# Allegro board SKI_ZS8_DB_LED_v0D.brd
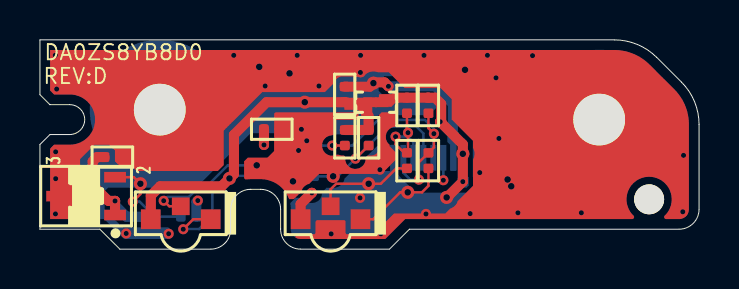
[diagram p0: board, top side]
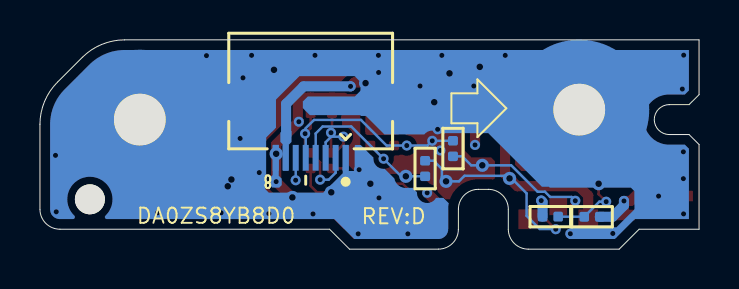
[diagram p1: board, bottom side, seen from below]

Outline 33 x 10.5 mm; copper layers: TOP, SGND, IN1, IN2, SVCC, IN3, SGND1, BOTTOM. Coordinates in mm from the lower left corner of the outline.
Outline path: 0,10.5 28.76,10.5 arc(29.91,10.27) 30.88,9.62 32.12,8.38 arc(32.77,7.41) 33,6.26 33,2 arc(32.71,1.29) 32,1 18.5,1 17.5,0 13.05,0 arc(12.34,0.29) 12.05,1 12.05,2 arc(11.76,2.71) 11.05,3 10.55,3 arc(9.84,2.71) 9.55,2 9.55,1 arc(9.26,0.29) 8.55,0 4,0 3,1 0,1 0,5.25 0.5,5.75 1.5,5.75 arc(2.25,6.5) 1.5,7.25 0.5,7.25 0,7.75 0,10.5

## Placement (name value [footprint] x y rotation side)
C7  0.1u/10v_4  [CC0402]  3.63 4.62 180 top
CN5048  led db  [50501-0080N-001-8P-L]  19.44 7.38 0 bottom
D4  *0.2pf/5v_4  [RC0402]  11.61 6.02 180 top
D6  *0.2pf/5v_4  [RC0402]  7.44 1.63 180 bottom
HE1  em-6781-t3  [SOT23_123-2_8-1_9]  2.31 2.66 0 top
HOLE1  *h-tc276bc102d102pt  [H-TC276BC102D102PT]  28 6.5 180 bottom
HOLE2  *h-c59d59n  [H-C59D59N]  30.5 2.5 0 top
HOLE3  *h-tc276bc102d102pt  [H-TC276BC102D102PT]  6 7 180 bottom
LED1  dual_light  [LEDLTST-S326KGJRKT-3P-SMT]  7.05 1.5 180 top
LED2  dual_light  [LEDLTST-S326KGJRKT-3P-SMT]  14.55 1.5 180 top
NOREF  -  []  -34.82 -54.97 0 top
NOREF#2  -  []  17.63 31.5 0 top
R1  *1m_4  [RC0402]  15.27 5.59 270 top
R2  *1m_4  [RC0402]  16.46 5.59 270 top
R3  300_4  [RC0402]  12.32 5.05 90 bottom
R4  680_4  [RC0402]  13.71 4.04 270 bottom
R5  *1m_4  [RC0402]  18.38 7.21 270 top
R6  *1m_4  [RC0402]  19.45 7.21 270 top
R7  300_4  [RC0402]  18.38 4.44 90 top
R8  680_4  [RC0402]  19.45 4.44 90 top
R9  *0_4  [RC0402]  15.26 7.76 90 top
R10  *short_4  [SHORT0402]  16.83 7.37 0 top
R11  *100k_4  [RC0402]  5.36 1.62 0 bottom

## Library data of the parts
C7 = CC0402
CN5048 = 50501-0080N-001-8P-L
D4 D6 R1-R9 R11 = RC0402
HE1 = SOT23_123-2_8-1_9
HOLE1 HOLE3 = H-TC276BC102D102PT
HOLE2 = H-C59D59N
LED1 LED2 = LEDLTST-S326KGJRKT-3P-SMT
R10 = SHORT0402

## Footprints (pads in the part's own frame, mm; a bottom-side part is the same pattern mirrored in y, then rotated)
50501-0080N-001-8P-L
  rect 0.305x1.295 smd: 1(-1.75,2.8) 2(-1.25,2.8) 3(-0.75,2.8) 4(-0.25,2.8) 5(0.25,2.8) 6(0.75,2.8) 7(1.25,2.8) 8(1.75,2.8)
  rect 1.803x1.397 smd: 9(-3.4,0) 10(3.4,0)
CC0402
  custom 0.12x0.12 smd: 1(0.39,0) 2(-0.39,0)
H-C59D59N
  round 1.499 hole 1.499 unplated: (0,0)
H-TC276BC102D102PT
  round 2.591 hole 2.591: 1(0,0)
LEDLTST-S326KGJRKT-3P-SMT
  rect 0.991x0.991 smd: 1(-1.5,0) 3(1.5,0)
  rect 0.889x0.889 smd: 2(0,-0.65)
RC0402
  custom 0.12x0.12 smd: 1(0.39,0) 2(-0.39,0)
SHORT0402
  rect 0.648x0.5 smd: 1(-0.39,0) 2(0.39,0)
SOT23_123-2_8-1_9
  rect 1.092x0.533 smd: 1(1.45,-0.95) 2(1.45,0.95) 3(-1.45,0)

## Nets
+3V3_PCU: C7.1 CN5048.8 D4.1 HE1.1 LED2.3 R5.2 R6.2 R10.2 R11.2
+3V3_S5: CN5048.7 R9.1
GND: C7.2 CN5048.1 CN5048.9 CN5048.10 D4.2 D6.2 HE1.3 HOLE1.1 HOLE3.1
BATLED0#: CN5048.3 R5.1 R7.1
BATLED1#: CN5048.2 R6.1 R8.1
LID2#: CN5048.6 D6.1 HE1.2 R11.1
PWRLED#: CN5048.5 R1.1 R3.1
SUSLED#: CN5048.4 R2.1 R4.1
N17522293: LED1.3 R1.2 R2.2 R9.2 R10.1
N17522305: LED1.2 R3.2
N17522342: LED2.2 R7.2
N17531645: LED2.1 R8.2
N17531780: LED1.1 R4.2

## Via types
v1: diameter 0.66, hole 0.33, TOP to BOTTOM, 16 vias
v2: diameter 0.508, hole 0.254, TOP to BOTTOM, 50 vias

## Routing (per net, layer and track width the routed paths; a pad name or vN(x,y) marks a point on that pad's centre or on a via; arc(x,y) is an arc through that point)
+3V3_PCU: length 38
  TOP w0.508: C7.1 2.86,4.62 2.64,4.4 2.64,3.21 3.43,2.42 v2(3.76,2.42) HE1.1 ; 17.8,7.6 R5.2 R6.2 19.78,7.6 20.09,7.29 20.09,6.44 v2(20.04,6.39) 21.17,5.26 v1(21.17,4.78) v2(21.17,3.39) 20.38,2.59 v1(20.36,2.59) ; D4.1 v2(11.22,5.23) ; v2(13.61,2.82) 13.05,2.26 LED2.3
  IN2 w0.508: v2(11.22,5.23) 10.84,4.86 9.31,4.86 7.63,3.18 4.52,3.18 v2(3.76,2.42) ; v2(11.22,5.23) 11.2,5.25 11.2,6.05 11.81,6.66 19.77,6.66 v2(20.04,6.39) ; v2(11.22,5.23) 13.59,2.86 13.59,2.85 v2(13.61,2.82)
  BOTTOM w0.508: v2(3.76,2.42) 3.76,2.19 4.33,1.62 R11.2
+3V3_S5: length 7.5
  TOP w0.508: v2(17.45,8.17) 17.25,8.37 16.73,8.37 v1(16.7,8.33) 16.52,8.15 R9.1
  BOTTOM w0.508: v2(17.45,8.17) 19.8,8.17 20.67,7.29 20.67,5.76
GND: length 1.9
  TOP w0.508: v2(13.09,6.01) 13.08,6.02 D4.2
  BOTTOM w0.508: v2(7.9,2.44) 7.83,2.37 D6.2
  vias: v1(10.98,9.15) v1(12.5,8.82) v1(21.28,9) v1(23.41,3.49) v1(23.6,3.16) v2(0.77,9.73) v2(0.84,8.03) v2(0.79,4.88) v2(0.79,3.54) v2(0.78,1.77) v2(2.03,2.66) v2(4.32,0.79) v2(6.45,0.77) v2(9.7,9.72) v2(11.28,8.18) v2(12.88,9.72) v2(12.95,4.95) v2(13.97,8.18) v2(14.58,0.77) v2(16.03,2.57) v2(16.05,9.72) v2(16.04,8.86) v2(17.02,3.99) v2(17.07,0.77) v2(19.23,9.72) v2(19.33,1.77) v2(21.54,1.78) v2(22.02,3.84) v2(22.4,9.72) v2(22.83,8.59) v2(22.98,5.55) v2(23.93,1.82) v2(24.66,9.71) v2(27.11,1.82) v2(32.22,4.7) v2(32.18,1.87)
BATLED0#: length 5
  TOP w0.127: R5.1 18.38,5.89 v2(18.43,5.84) 18.43,4.88 R7.1 18.24,4.83 17.8,5.26 v2(17.8,5.64)
  BOTTOM w0.127: CN5048.3 18.69,5.36 18.42,5.64 v2(17.8,5.64)
BATLED1#: length 5.4
  TOP w0.127: R6.1 19.45,6.07 v2(19.73,5.79) 19.73,5.11 R8.1 18.97,4.35 v2(18.97,3.49)
  BOTTOM w0.127: v2(18.97,3.49) 18.54,3.49 18.2,3.83 CN5048.2
LID2#: length 23.2
  TOP w0.127: v2(4.65,2.38) 5.03,2.76 v1(5.03,3.28) 4.7,3.61 HE1.2
  IN1 w0.127: v2(4.65,2.38) 5.48,3.21 7.8,3.21 8.68,4.09 16.28,4.09 17.42,2.95 19.69,2.95 v2(20.2,3.46)
  BOTTOM w0.127: v2(4.65,2.38) 4.99,2.38 R11.1 5.75,1.63 D6.1 ; v2(20.2,3.46) 20.2,3.46 CN5048.6
PWRLED#: length 10.3
  TOP w0.127: R1.1 14.69,5.2 14.69,5.2 v2(14.64,5.2)
  BOTTOM w0.127: R3.1 13.36,5.44 v2(13.36,5.44) 13.6,5.2 v2(14.64,5.2) 15.64,5.2 16.93,6.48 19.28,6.48 19.69,6.07 CN5048.5
SUSLED#: length 8.8
  TOP w0.127: R2.1 15.8,4.54 v2(15.8,4.54)
  BOTTOM w0.127: CN5048.4 19.2,5.8 18.85,6.15 17.41,6.15 v2(15.8,4.54) 14.91,3.65 v1(14.68,3.65) R4.1
N17522293: length 15.9
  TOP w0.508: LED1.3 5.55,2.69 6.02,3.16 9.1,3.16 v1(9.49,3.55) 9.71,3.77 9.71,5.74 11.35,7.37 v1(13.26,7.37) R9.2 15.26,7.37 ; 16.46,6.69 R2.2 R1.2
N17522305: length 8
  TOP w0.127: v2(6.2,2.43) 6.47,2.15 LED1.2
  BOTTOM w0.127: R3.2 11.86,4.66 11.41,4.21 v1(10.85,4.21) 9.41,4.21 8.08,2.88 7.72,2.88 7.46,2.62 6.39,2.62 v2(6.2,2.43)
N17522342: length 5.1
  TOP w0.127: LED2.2 14.55,3 14.83,3.28 v1(16.46,3.28) 17.07,3.28 17.84,4.05 R7.2
N17531645: length 5
  TOP w0.127: R8.2 19.45,3.18 19.13,2.85 v1(18.41,2.85) 18.03,2.85 16.68,1.5 LED2.1
N17531780: length 10.7
  TOP w0.127: v2(7.17,1) 7.67,1.5 LED1.1
  BOTTOM w0.127: R4.2 13.28,4.43 12.88,4.03 12.88,3.61 v1(12.67,3.4) 12.02,3.4 11.74,3.68 9.51,3.68 8.63,2.8 8.63,1.67 7.97,1.01 7.18,1.01 v2(7.17,1)

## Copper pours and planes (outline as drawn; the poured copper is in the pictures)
+3V3_PCU on BOTTOM (solid shape): 21.35,5.2 21.35,3.72 21.47,3.6 21.47,3.19 21.36,3.09 21.02,3.09 20.89,3.21 20.89,3.54 21.04,3.69 21.04,5.21 21.07,5.23 21.32,5.23
+3V3_S5 on BOTTOM (solid shape): 20.96,5.85 20.96,5.38 20.85,5.27 20.85,3.96 20.82,3.94 20.57,3.94 20.55,3.96 20.55,5.23 20.4,5.38 20.4,5.9 20.45,5.95 20.86,5.95
GND on TOP (solid shape): 15.86,6.86 15.95,6.77 15.95,6.56 15.87,6.49 14.82,6.49 14.73,6.39 14.73,5.8 14.63,5.71 14.61,5.71 14.14,5.08 14.85,4.73 14.86,4.74 14.96,4.74 15.04,4.71 15.12,4.7 15.19,4.7 15.26,4.67 15.29,4.59 15.78,4.03 16.3,4.57 16.3,4.59 16.41,4.7 16.61,4.7 16.86,4.81 16.96,5.06 16.96,5.35 16.96,5.76 16.97,5.77 16.97,5.99 16.97,6.72 17.11,6.86 17.78,6.86 17.88,6.77 17.9,6.71 17.93,6.65 17.93,6.55 17.92,6.53 17.88,6.45 17.87,6.35 17.87,6.19 17.82,6.14 17.8,6.14 17.35,5.8 17.49,5.25 17.51,5.24 17.51,5.16 17.81,4.86 17.81,4.48 17.11,3.77 13.98,3.77 13.47,3.27 13.23,3.13 13.09,2.89 12.71,2.5 12.47,2.5 11.92,3.23 11.05,3.51 10.55,3.51 10.44,3.5 10.34,3.49 10.26,3.52 10.22,3.59 10.22,4.41 10.41,4.59 11.39,4.59 11.73,4.93 11.73,5.8 11.73,6.23 11.73,6.8 11.79,6.86 15.05,6.86
GND on TOP (solid shape): outline of 92 points within 0.51,0.51 32.49,9.99
GND on BOTTOM (solid shape): outline of 105 points within 0.51,0.51 32.49,9.99
GND on SGND (solid shape): 28.76,9.99 29.71,9.8 30.52,9.26 31.76,8.02 32.3,7.21 32.49,6.26 32.49,2 32.35,1.65 32,1.51 31.96,1.51 31.35,1.51 31.26,1.57 31.28,1.68 30.5,3.63 29.72,1.68 29.74,1.57 29.65,1.51 28.95,1.51 28.95,1.51 18.29,1.51 17.29,0.51 13.05,0.51 12.7,0.65 12.56,1 12.56,2 12.12,3.07 11.05,3.51 10.55,3.51 9.48,3.07 9.04,2 9.04,1 8.9,0.65 8.55,0.51 4.21,0.51 3.21,1.51 0.51,1.51 0.51,5.04 0.71,5.24 1.5,5.24 2.76,6.5 1.5,7.76 0.71,7.76 0.51,7.96 0.51,9.99
GND on IN1 (solid shape): outline of 842 points within 0.51,0.51 32.49,9.99
GND on IN2 (solid shape): outline of 753 points within 0.51,0.51 32.49,9.99
GND on SVCC (solid shape): 28.76,9.99 29.71,9.8 30.52,9.26 31.76,8.02 32.3,7.21 32.49,6.26 32.49,2 32.35,1.65 32,1.51 31.96,1.51 31.35,1.51 31.26,1.57 31.28,1.68 30.5,3.63 29.72,1.68 29.74,1.57 29.65,1.51 28.95,1.51 28.95,1.51 18.29,1.51 17.29,0.51 13.05,0.51 12.7,0.65 12.56,1 12.56,2 12.12,3.07 11.05,3.51 10.55,3.51 9.48,3.07 9.04,2 9.04,1 8.9,0.65 8.55,0.51 4.21,0.51 3.21,1.51 0.51,1.51 0.51,5.04 0.71,5.24 1.5,5.24 2.76,6.5 1.5,7.76 0.71,7.76 0.51,7.96 0.51,9.99
GND on IN3 (solid shape): outline of 949 points within 0.51,0.51 32.49,9.99
GND on SGND1 (solid shape): 28.76,9.99 29.71,9.8 30.52,9.26 31.76,8.02 32.3,7.21 32.49,6.26 32.49,2 32.35,1.65 32,1.51 31.96,1.51 31.35,1.51 31.26,1.57 31.28,1.68 30.5,3.63 29.72,1.68 29.74,1.57 29.65,1.51 28.95,1.51 28.95,1.51 18.29,1.51 17.29,0.51 13.05,0.51 12.7,0.65 12.56,1 12.56,2 12.12,3.07 11.05,3.51 10.55,3.51 9.48,3.07 9.04,2 9.04,1 8.9,0.65 8.55,0.51 4.21,0.51 3.21,1.51 0.51,1.51 0.51,5.04 0.71,5.24 1.5,5.24 2.76,6.5 1.5,7.76 0.71,7.76 0.51,7.96 0.51,9.99
N17522293 on TOP (solid shape): 16.64,7.55 16.64,6.74 16.59,6.69 16.13,6.69 16.09,6.7 16.08,6.74 16.08,6.83 15.91,6.99 15.26,6.99 15.24,7.02 15.24,7.52 15.32,7.6 16.59,7.6

Small or netless copper shapes (teardrops, artwork), in the pictures only: 1 on TOP, 1 on IN2

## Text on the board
Ref Des/Silkscreen Bottom: REV:D | DA0ZS8YB8D0
Ref Des/Silkscreen Top: REV:D | DA0ZS8YB8D0
User.9: 8
User.45: FIGURE | TYPE | Circle | SIZE | 10.0 | 102.0 | 59.0 | DRILL CHART: TOP to BOTTOM | ALL UNITS ARE IN MILS | PLATED | NON-PLATED | ROTATION | - | QTY | 47 | 2 | 1 | 50 | TOTAL HOLES:
